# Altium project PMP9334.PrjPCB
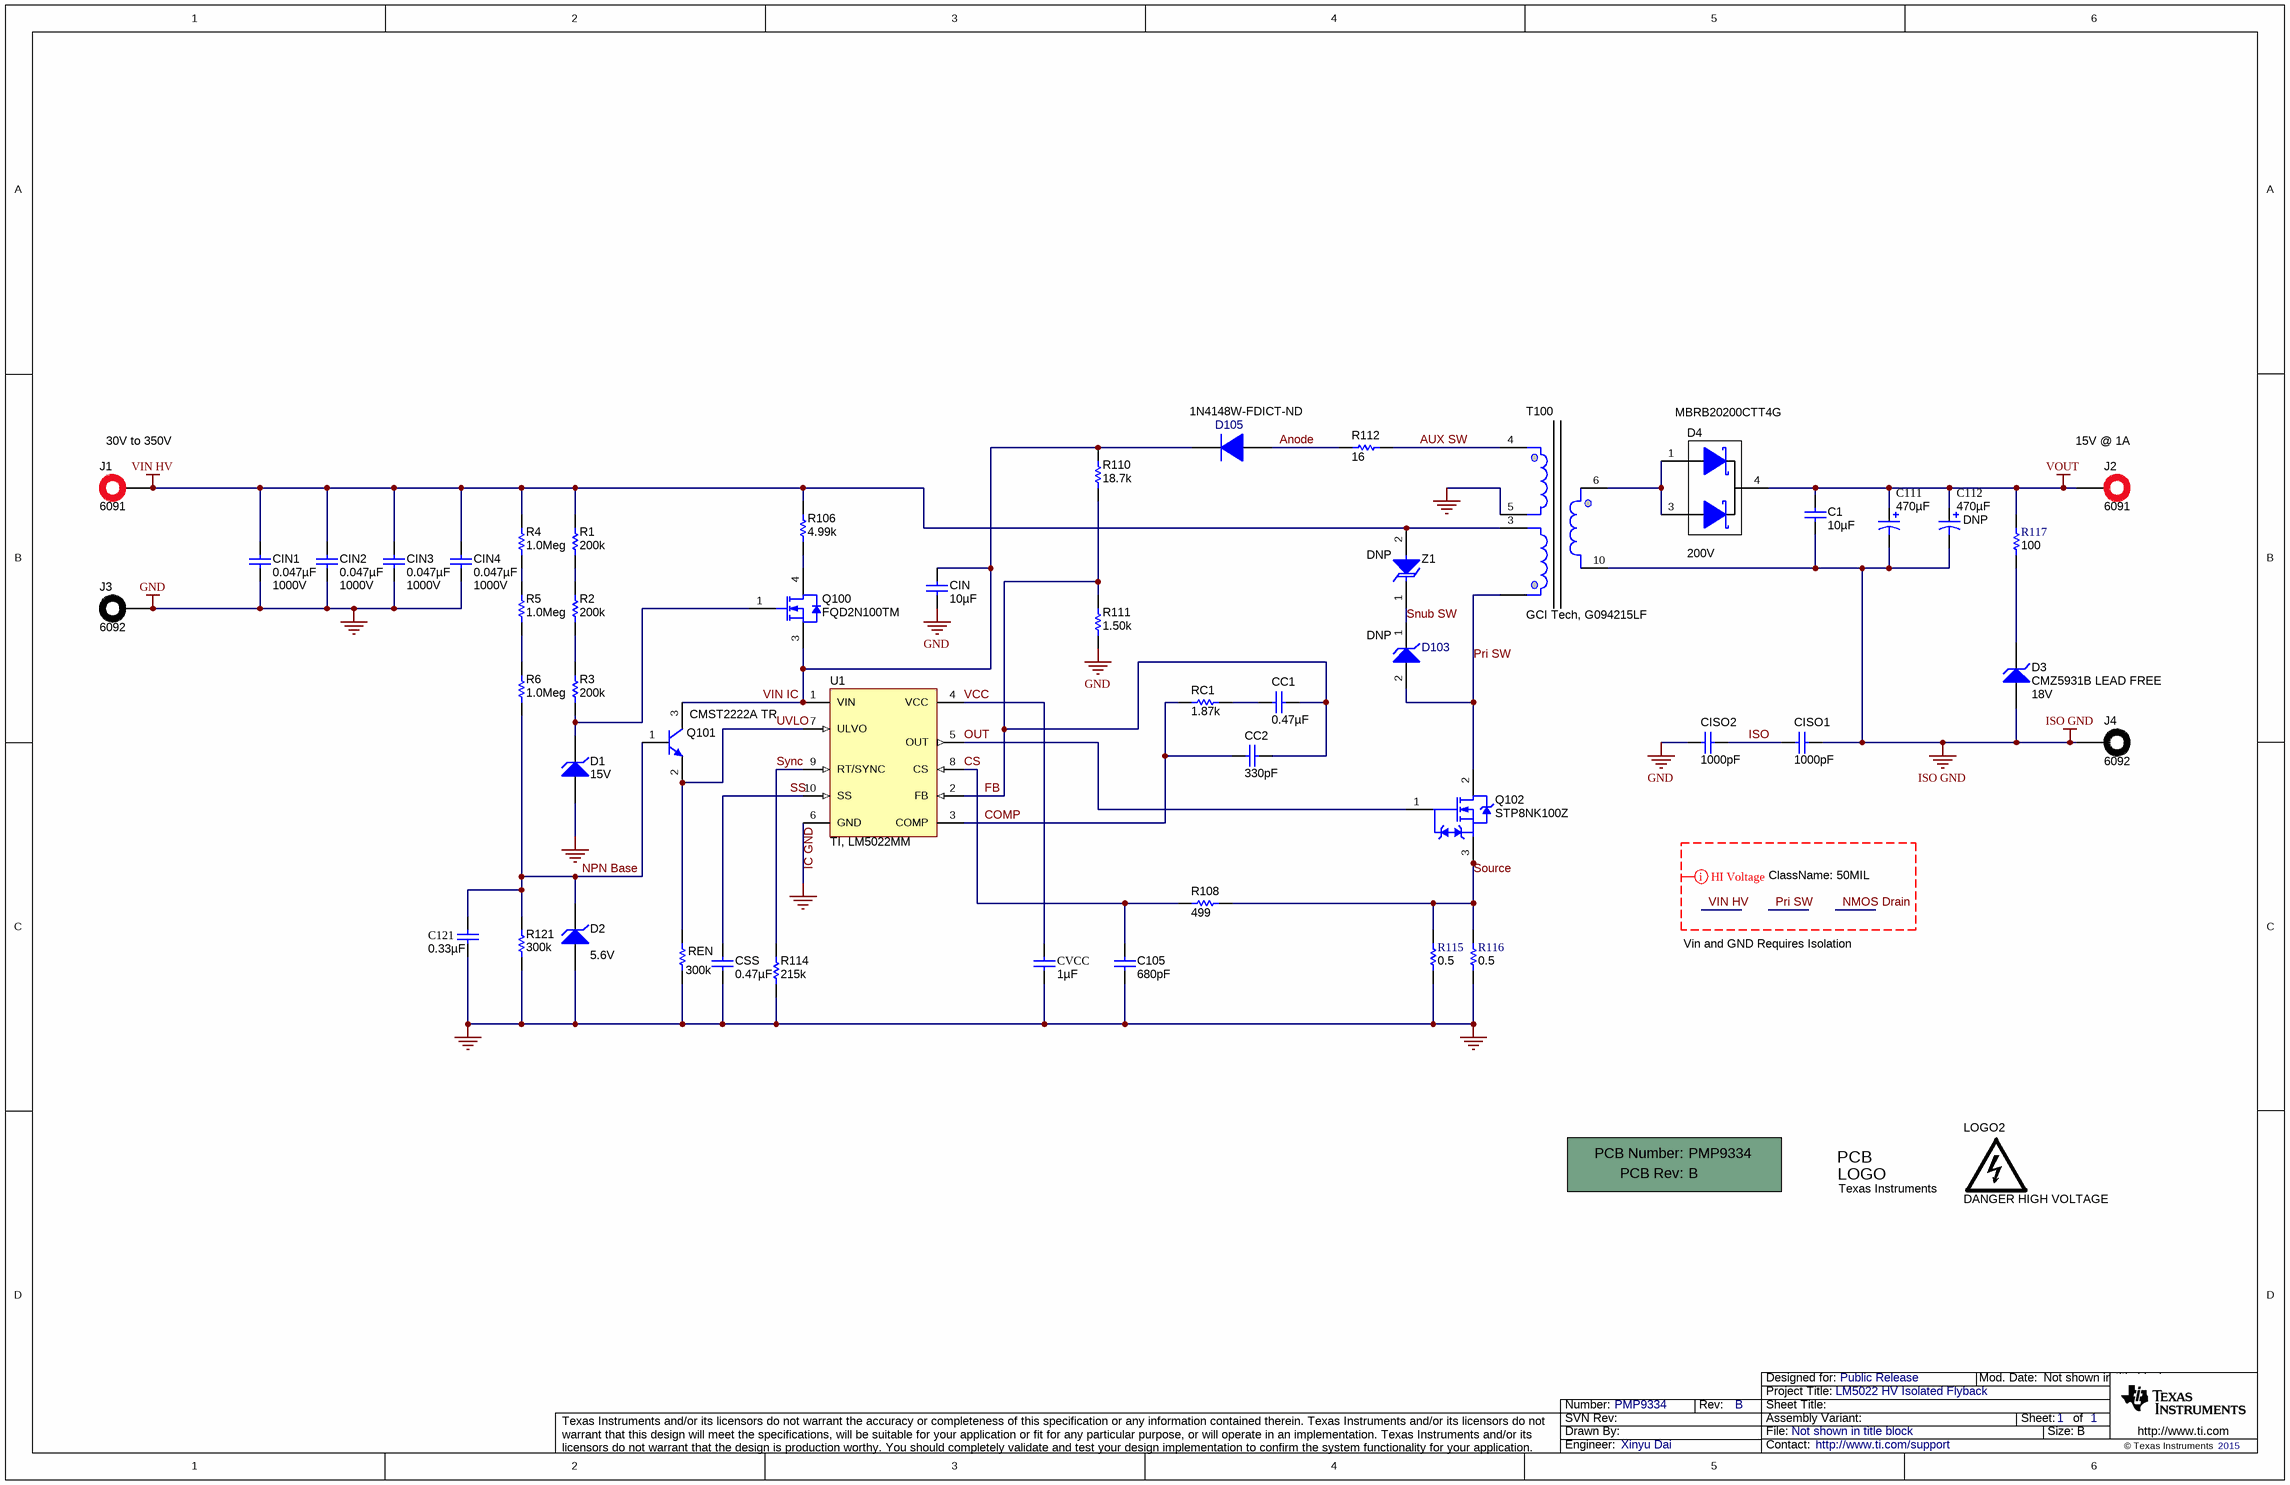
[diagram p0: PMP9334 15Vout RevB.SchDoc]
TID: PMP9334; TechSupport: http://www.ti.com/support; SCH_Rev: B; PRJ_Title: LM5022 HV Isolated Flyback; PRJ_Number: PMP9334; PRJ_Engineer: Xinyu Dai; PRJ_Customer: Public Release; PCB_Rev: B; PCB_Layout: Xinyu Dai; CopyrightYear: 2015
1 sheet, 53 parts. Net scope: global (net labels, ports and power ports of the same name join across sheets).
Board file: PMP9334 RevB.PcbDoc

## Sheet PMP9334 15Vout RevB.SchDoc
size 431 x 279 mm; Date: Not shown in title block; ApprovedBy: Not shown in title block; CheckedBy: Not shown in title block; Author: Not shown in title block; CompanyName: Not shown in title block; Engineer: Not shown in title block; Organization: Not shown in title block; Address1: Not shown in title block; Address2: Not shown in title block; Address3: Not shown in title block; Address4: Not shown in title block; DocumentNumber: 1; Revision: Use project parameter SCH_Rev; SheetNumber: 1; SheetTotal: 1; PageSetup: Record=PageOptions¦CenterHorizontal=True¦CenterVertical=True¦PrintScale=0.96¦XCorrection=1.00¦YCorrection=1.00¦PrintKind=0¦BorderSize=5000000¦LeftOffset=0¦BottomOffset=0¦Orientation=2¦PaperLength=1000¦PaperWidth=1000¦Scale=100¦PaperSource=15¦PrintQuality=600¦MediaType=1¦DitherType=10¦PaperKind=11x17¦PrintScaleMode=1

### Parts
!PCB  Printed Circuit Board  (value not drawn)  (mechanical)
C1  ValueDisplayed: 10µF  [2220]  (hidden comment: TDK, C5750X7S2A106M)
C105  ValueDisplayed: 680pF  [0603]  (hidden comment: C0603C681K5RACTU)
C111  ValueDisplayed: 470µF  [CAPSMT_62_KE0]  (hidden comment: EMVY350ATR471MKE0S)
C112  DNP  ValueDisplayed: 470µF  [CAPSMT_62_KE0]
C121  ValueDisplayed: 0.33µF  [0805_HV]  (hidden comment: GRM21BR71E334KA01L)
CC1  ValueDisplayed: 0.47µF  [0603]  (hidden comment: C0603C474K4RACTU)
CC2  ValueDisplayed: 330pF  [0603]  (hidden comment: C0603C331K5RACTU)
CIN  ValueDisplayed: 10µF  [0805_HV]  (hidden comment: C2012X5R1E106K125AB)
CIN1  ValueDisplayed: 0.047µF  Value2: 1000V  [1812]  (hidden comment: C1812V473KDRACTU)
CIN2  ValueDisplayed: 0.047µF  Value2: 1000V  [1812]  (hidden comment: C1812V473KDRACTU)
CIN3  ValueDisplayed: 0.047µF  Value2: 1000V  [1812]  (hidden comment: C1812V473KDRACTU)
CIN4  ValueDisplayed: 0.047µF  Value2: 1000V  [1812]  (hidden comment: C1812V473KDRACTU)
CISO1  ValueDisplayed: 1000pF  [1210]  (hidden comment: VJ1210A102JXGAT5Z)
CISO2  ValueDisplayed: 1000pF  [1210]  (hidden comment: VJ1210A102JXGAT5Z)
CSS  ValueDisplayed: 0.47µF  [0603]  (hidden comment: C0603C474K4RACTU)
CVCC  ValueDisplayed: 1µF  [0603L]  (hidden comment: GRM188R61E105KA12D)
D1  value 15V  [SMA]  (hidden comment: CMZ5929B TR13)
D2  value 5.6V  [SMA]  (hidden comment: CMZ5919B TR13)
D3  CMZ5931B LEAD FREE  value 18V  [SMA]
D4  MBRB20200CTT4G  value 200V  [DDPAK]
D103  DNP  [SMB]  (value not drawn)
D105  Supplier Part Number 1: 1N4148W-FDICT-ND  [SOD-123]  (hidden comment: 1N4148W-7-F)
J1  6091  [6091]
J2  6091  [6091]
J3  6092  [6092]
J4  6092  [6092]
Logo1  Texas Instruments  [TI_Stacked_SolderMask_Small]  (no BOM)
LOGO2  DANGER HIGH VOLTAGE  [IEC_HighVoltage_Large]  (no BOM)
Q100  FQD2N100TM  [DPAK]
Q101  CMST2222A TR  [SOT-323]
Q102  STP8NK100Z  [TO-220AB]
R1  value 200k  [0805_HV]  (hidden comment: CRCW0805200KJNEA)
R2  value 200k  [0805_HV]  (hidden comment: CRCW0805200KJNEA)
R3  value 200k  [0805_HV]  (hidden comment: CRCW0805200KJNEA)
R4  value 1.0Meg  [0805_HV]  (hidden comment: CRCW08051M00JNEA)
R5  value 1.0Meg  [0805_HV]  (hidden comment: CRCW08051M00JNEA)
R6  value 1.0Meg  [0805_HV]  (hidden comment: CRCW08051M00JNEA)
R106  value 4.99k  [1206]  (hidden comment: CRCW12064K99FKEA)
R108  ValueDisplayed: 499  [0603]  (hidden comment: CRCW0603499RFKEA)
R110  value 18.7k  [0603]  (hidden comment: DNP)
R111  ValueDisplayed: 1.50k  [0603]  (hidden comment: CRCW06031K50FKEA)
R112  value 16  [0603]  (hidden comment: CRCW060316R0JNEA)
R114  ValueDisplayed: 215k  [0603]  (hidden comment: CRCW0603215KFKEA)
R115  ValueDisplayed: 0.5  [2010]  (hidden comment: CSRN2010FKR500)
R116  ValueDisplayed: 0.5  [2010]  (hidden comment: CSRN2010FKR500)
R117  value 100  [1206]
R121  value 300k  [0603]  (hidden comment: RC0603FR-07300KL)
RC1  ValueDisplayed: 1.87k  [0603]  (hidden comment: CRCW06031K87FKEA)
REN  value 300k  [0603]  (hidden comment: RC0603FR-07300KL)
T100  GCI Tech, G094215LF  [G094215LF r 0]
U1  TI, LM5022MM  [MUB10A_N]
Z1  DNP  [SMA]  (value not drawn)

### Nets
GND: C105.2 C121.2 CIN.2 CIN1.2 CIN2.2 CIN3.2 CIN4.2 CISO2.2 CSS.2 CVCC.2 D1.2(A) D2.2(A) J3.1 R111.1 R114.1 R115.1 R116.1 R121.1 REN.1 T100.5 U1.6(GND)
ISO GND: C1.2 C111.2(-) C112.2(-) CISO1.1 D3.2(A) J4.1 T100.10
VIN HV: CIN1.1 CIN2.1 CIN3.1 CIN4.1 J1.1 R1.2 R4.2 R106.2 T100.3 Z1.2(A)
VOUT: C1.1 C111.1(+) C112.1(+) D4.4(K) J2.1 R117.2
Anode: D105.2(A) R112.2
AUX SW: R112.1 T100.4
COMP: CC2.2 RC1.1 U1.3(COMP)
CS: C105.1 R108.1 U1.8(CS)
FB: CC1.1 CC2.1 R110.1 R111.2 U1.2(FB)
ISO: CISO1.2 CISO2.1
NPN Base: C121.1 D2.1(K) Q101.1(B) R6.1 R121.2
OUT: Q102.1(G) U1.5(OUT)
Pri SW: D103.2(A) Q102.2(D) T100.1
Snub SW: D103.1(K) Z1.1(K)
Source: Q102.3(S) R108.2 R115.2 R116.2
SS: CSS.1 U1.10(SS)
Sync: R114.2 U1.9(RT/SYNC)
UVLO: Q101.2(E) REN.2 U1.7(ULVO)
VCC: CVCC.1 U1.4(VCC)
VIN IC: CIN.1 D105.1(K) Q100.3(S) Q101.3(C) R110.2 U1.1(VIN)
NetCC1_2: CC1.2 RC1.2
NetD1_1: D1.1(K) Q100.1(G) R3.1
NetD3_1: D3.1(K) R117.1
NetD4_1: D4.1(A) D4.3(A) T100.6
NetQ100_4: Q100.4(D) R106.1
NetR1_1: R1.1 R2.2
NetR2_1: R2.1 R3.2
NetR4_1: R4.1 R5.2
NetR5_1: R5.1 R6.2

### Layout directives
net class 50MIL: NMOS Drain, Pri SW, VIN HV

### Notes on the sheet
- (near J1) 30V to 350V
- (near J2) 15V @ 1A
- (near Z1) DNP
- (near D103) DNP
- Vin and GND Requires Isolation
- Labels drawn without touching a wire or pin: IC GND

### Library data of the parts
!PCB = PCB: Manufacturer: Any; PartNumber: PMP9334; SymbolCreator: a0412235
C1 = C5750X7S2A106M: CAP, CERM, 10uF, 100V, +/-20%, X7S, 2220; Polarized: N; CompType: Capacitor; U/M: EA; Cap_F: 0.00001; Tolerance_%: 20; ESR_Ohm: 0.005; Value1: 0.005 ohm; VDC_V: 100; IRMS_A: 6.45; TaMin_C: -55; TaMax_C: 125
C105 = C0603C681K5RACTU: CAP, CERM, 680 pF, 50 V, +/- 10%, X7R, 0603; Manufacturer: Kemet; Polarized: N; CompType: Capacitor; Value: 680pF; U/M: EA; Cap_F: 0.00000000068; Tolerance_%: 10; Value1: Unknown; VDC_V: 50; Value2: 50V; TaMin_C: -55; TaMax_C: 125
C111 C112 = EMVY350ATR471MKE0S: CAP, AL, 470uF, 35V, +/-20%, 0.07 ohm, SMD; Manufacturer: Nippon Chemi-Con; Cap_Case: KE0; ESR_Ohm: 0.07; IRMS_A: 0.82; Polarized: Y; TaMax_C: 105; TaMin_C: -55; Tolerance_%: 20; VDC_V: 35; CompType: Capacitor; Cap_F: 0.00047; U/M: EA
C121 = GRM21BR71E334KA01L: CAP, CERM, 0.33uF, 25V, +/-10%, X7R, 0805; Manufacturer: MuRata; Cap_Case: 0805; Polarized: N; TaMax_C: 125; TaMin_C: -55; Tolerance_%: 10; VDC_V: 25; Cap_F: 0.00000033; CompType: Capacitor; Value1: Unknown; U/M: EA
CC1 CSS = C0603C474K4RACTU: CAP, CERM, 0.47 µF, 16 V, +/- 10%, X7R, 0603; Manufacturer: Kemet; Polarized: N; CompType: Capacitor; Value: 0.47uF; U/M: EA; Cap_F: 0.00000047; Tolerance_%: 10; Value1: Unknown; VDC_V: 16; Value2: 16V; TaMin_C: -55; TaMax_C: 125
CC2 = C0603C331K5RACTU: CAP, CERM, 330 pF, 50 V, +/- 10%, X7R, 0603; Manufacturer: Kemet; Polarized: N; CompType: Capacitor; Value: 330pF; U/M: EA; Cap_F: 0.00000000033; Tolerance_%: 10; Value1: Unknown; VDC_V: 50; Value2: 50V; TaMin_C: -55; TaMax_C: 125
CIN = C2012X5R1E106K125AB: CAP, CERM, 10 µF, 25 V, +/- 10%, X5R, 0805; Manufacturer: TDK; Polarized: N; CompType: Capacitor; Value: 10uF; U/M: EA; Cap_F: 0.00001; Tolerance_%: 10; Value1: Unknown; VDC_V: 25; Value2: 25V; TaMin_C: -55; TaMax_C: 85; Cap_Case: 0805
CIN1-CIN4 = C1812V473KDRACTU: CAP, CERM, 0.047 µF, 1000 V, +/- 10%, X7R, 1812; Manufacturer: Kemet; Polarized: N; CompType: Capacitor; Value: 0.047uF; U/M: EA; Cap_F: 0.000000047; Tolerance_%: 10; Value1: Unknown; VDC_V: 1000; TaMin_C: -55; TaMax_C: 125
CISO1 CISO2 = VJ1210A102JXGAT5Z: CAP, CERM, 1000 pF, 1000 V, +/- 5%, C0G/NP0, 1210; Manufacturer: Vishay-Vitramon; Polarized: N; CompType: Capacitor; Value: 1000pF; U/M: EA; Cap_F: 0.000000001; Tolerance_%: 5; Value1: Unknown; VDC_V: 1000; Value2: 1000V; TaMin_C: -55; TaMax_C: 125
CVCC = GRM188R61E105KA12D: CAP, CERM, 1 µF, 25 V, +/- 10%, X5R, 0603; Manufacturer: MuRata; Cap_Case: 0603; Polarized: N; TaMax_C: 85; TaMin_C: -55; Tolerance_%: 10; VDC_V: 25; Cap_F: 0.000001; CompType: Capacitor; Value: 1uF; Value1: Unknown; Value2: 25V; U/M: EA
D1 = CMZ5929B TR13: Diode, Zener, 15 V, 1.5 W, SMA; Manufacturer: Central Semiconductor; SymbolCreator: a0412235; U/M: EA; Power_W: 1.5; Vz_V: 15; Value1: 1.5W; RJA_CperW: 250
D2 = CMZ5919B TR13: Diode, Zener, 5.6 V, 1.5 W, SMA; Manufacturer: Central Semiconductor; SymbolCreator: a0412235; U/M: EA; Power_W: 1.5; Vz_V: 5.6; Value1: 1.5W; RJA_CperW: 250
D3 = CMZ5931B LEAD FREE: Diode, Zener, 18 V, 900 mW, SMA; Manufacturer: Central Semiconductor; U/M: EA; Power_W: 0.9; Vz_V: 18; Value1: 0.9W; RJA_CperW: 139; SymbolCreator: a0412235
D4 = MBRB20200CTT4G: Diode, Schottky, 200V, 20A, DDPAK; Manufacturer: ON Semiconductor; U/M: EA; Vf_V: 1; Value2: 1V; Io_A: 20; Vr_V: 200; TJmax_C: 150; RJC_CperW: 2
D103 = 1SMB5934BT3G: Diode, Zener, 24V, 550mW, SMB; Manufacturer: ON Semiconductor; Power_W: 0.55; Value1: 0.55W; RJA_CperW: 226; U/M: EA; Vz_V: 24
D105 = 1N4148W-7-F: Diode, Ultrafast, 100V, 0.15A, SOD-123; Manufacturer: Diodes Inc.; Vf_V: 1.25; Io_A: 0.15; Vr_V: 100; TJmax_C: 150; Value: 1.25V; U/M: EA
J1 J2 = 6091: Standard Banana Jack, Insulated, Red; Manufacturer: Keystone; SymbolCreator: a0412235; CompType: Connector; U/M: EA
J3 J4 = 6092: Standard Banana Jack, Insulated, Black; Manufacturer: Keystone; SymbolCreator: a0412235; CompType: Connector; U/M: EA
Logo1 = TI_Logo: Texas Instrument Corporate Signature; SymbolCreator: a0412235
LOGO2 = IEC_HighVoltage: IEC 61010-1 High Voltage Warning; SymbolCreator: a0412235
Q100 = FQD2N100TM: MOSFET, N-CH, 1000 V, 1.6 A, DPAK; Manufacturer: Fairchild Semiconductor; Alternate Manufacturer: None; U/M: EA; ChType: N; Value: 1000V; VdsMax_V: 1000; Value1: ? ohm; Value2: 12 nC; QgTyp_nC: 12; Vgs_V: 30; IdsMax_A: 1.6
Q101 = CMST2222A TR, Central Semiconductor: Transistor, NPN, 40 V, 0.6 A, SOT-323; CompType: BJT; PNP: 0; NPN: 1; Vceo_V: 40; Vcesat1_V: 0.3; Value: 40 V; IcRated_A: 0.6; Value1: 0.6 A; TaMin_C: -65; TaMax_C: 150; U/M: EA
Q102 = STP8NK100Z: MOSFET, N-CH, 1000 V, 6.5 A, TO-220AB; Manufacturer: STMicroelectronics; Alternate Manufacturer: None; U/M: EA; ChType: N; Value: 1000V; VdsMax_V: 1000; Value1: ? ohm; Value2: 73 nC; QgTyp_nC: 73; Vgs_V: 30; IdsMax_A: 6.5; SymbolCreator: x0208325
R1-R3 = CRCW0805200KJNEA: RES, 200k ohm, 5%, 0.125W, 0805; Manufacturer: Vishay-Dale; CompType: Resistor; Res_ohm: 200000; Tolerance_%: 5; Power_W: 0.125; VDC_V: 150; TempCo: 200 ppm/C; EIA_Code: E24; U/M: EA
R4-R6 = CRCW08051M00JNEA: RES, 1.0Meg ohm, 5%, 0.125W, 0805; Manufacturer: Vishay-Dale; CompType: Resistor; Res_ohm: 1000000; Value_Code: 1M00; Tolerance_%: 5; Power_W: 0.125; VDC_V: 150; TempCo: 200 ppm/C; EIA_Code: E24; U/M: EA
R106 = CRCW12064K99FKEA: RES, 4.99k ohm, 1%, 0.25W, 1206; Manufacturer: Vishay-Dale; CompType: Resistor; Res_ohm: 4990; Value_Code: 4k99; Tolerance_%: 1; Power_W: 0.25; VDC_V: 200; TempCo: 100 ppm/C; EIA_Code: E96; U/M: EA
R108 = CRCW0603499RFKEA: RES, 499, 1%, 0.1 W, 0603; Manufacturer: Vishay-Dale; CompType: Resistor; Value: 499; Value_Code: 499R; Tolerance_%: 1; Power_W: 0.1; Value2: 0.1W; VDC_V: 75; TempCo: 100 ppm/C; EIA_Code: E96; U/M: EA
R110 = RG1608P-1872-B-T5: RES, 18.7k ohm, 0.1%, 0.1W, 0603; Manufacturer: Susumu Co Ltd; CompType: Resistor; Res_ohm: 18700; Value_Code: 18k7; Tolerance_%: 0.1; VDC_V: 75; TempCo: 25 ppm/C; EIA_Code: E192; U/M: EA
R111 = CRCW06031K50FKEA: RES, 1.50 k, 1%, 0.1 W, 0603; Manufacturer: Vishay-Dale; CompType: Resistor; Value: 1.50k; Res_ohm: 1500; Value_Code: 1k50; Tolerance_%: 1; Power_W: 0.1; Value2: 0.1W; VDC_V: 75; TempCo: 100 ppm/C; EIA_Code: E96; U/M: EA
R112 = CRCW060316R0JNEA: RES, 16 ohm, 5%, 0.1W, 0603; Manufacturer: Vishay-Dale; CompType: Resistor; Value_Code: 16R0; Tolerance_%: 5; Power_W: 0.1; VDC_V: 75; TempCo: 200 ppm/C; EIA_Code: E24; U/M: EA
R114 = CRCW0603215KFKEA: RES, 215 k, 1%, 0.1 W, 0603; Manufacturer: Vishay-Dale; CompType: Resistor; Value: 215k; Res_ohm: 215000; Tolerance_%: 1; Power_W: 0.1; Value2: 0.1W; VDC_V: 75; TempCo: 100 ppm/C; EIA_Code: E96; U/M: EA
R115 R116 = CSRN2010FKR500: RES, 0.5, 1%, 1 W, 2010; Manufacturer: Stackpole Electronics Inc; CompType: Resistor; Tolerance_%: 1; Value: 0.5; Value_Code: R500; Value2: 1W; TempCo: 250 ppm/C; U/M: EA
R117 = CRCW1206100RFKEA: RES, 100 ohm, 1%, 0.25W, 1206; Manufacturer: Vishay-Dale; CompType: Resistor; Tolerance_%: 1; VDC_V: 200; Power_W: 0.25; Value_Code: 100R; EIA_Code: E96; TempCo: 100 ppm/C; U/M: EA
R121 REN = RC0603FR-07300KL: RES, 300k ohm, 1%, 0.1W, 0603; Manufacturer: Yageo America; CompType: Resistor; Res_ohm: 300000; Tolerance_%: 1; Power_W: 0.1; VDC_V: 150; TempCo: 200 ppm/C; U/M: EA
RC1 = CRCW06031K87FKEA: RES, 1.87 k, 1%, 0.1 W, 0603; Manufacturer: Vishay-Dale; CompType: Resistor; Value: 1.87k; Res_ohm: 1870; Value_Code: 1k87; Tolerance_%: 1; Power_W: 0.1; Value2: 0.1W; VDC_V: 75; TempCo: 100 ppm/C; EIA_Code: E96; U/M: EA
T100 = XFMR-EFD15-2P-1S: Transformer, 3mH
U1 = LM5022MM: 60V Low Side  Controller for Boost and SEPIC; Manufacturer: Texas Instruments; CompType: MiscPower; PackageTopMarking: ZXTT*5022
Z1 = SMAJ120A: Diode, TVS, Uni, 120V, 400W, SMA; Manufacturer: Littelfuse; U/M: EA; Power_W: 400; Vr_V: 120

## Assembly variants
001: not fitted C112 D103 Z1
